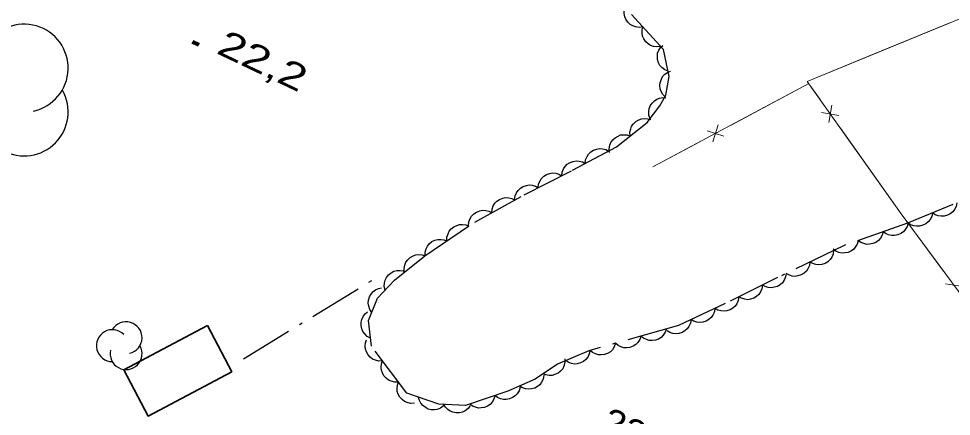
# Model space of a CAD drawing. Extents: x 356765 to 358572, y 5103174 to 5104650.
# Drawn here: x 357286.2 to 357339.2, y 5103854.6 to 5103877.1 of the extents above; entities that cross this region are included whole.
import ezdxf

# ---------------------------------------------------------------- set-up
doc = ezdxf.new("R2010")
doc.units = 0
doc.header["$LTSCALE"] = 0.6
doc.linetypes.add('DOT_DASHED', pattern=[7.7, 5, -1.2, 0.3, -1.2])
for name, color, linetype, lineweight in [('3', 7, 'Continuous', 140), ('31', 7, 'Continuous', 70), ('37', 7, 'Continuous', 13), ('41', 7, 'DOT_DASHED', 25), ('44', 7, 'Continuous', 25)]:
    doc.layers.add(name, color=color, linetype=linetype, lineweight=lineweight)

msp = doc.modelspace()

# ---------------------------------------------------------------- linework, layer by layer
at = {"layer": '3'}
msp.add_line((357296.1, 5103875.8), (357296.46, 5103875.63), dxfattribs=at)
at = {"layer": '31', "lineweight": 35}
msp.add_lwpolyline([(357296.95, 5103859.7), (357298.34, 5103857.08), (357293.6, 5103854.57), (357292.21, 5103857.19), (357296.95, 5103859.7)], close=True, dxfattribs=at)
at = {"layer": '37'}
for p, q in [((357339.09, 5103876.87), (357334.47, 5103874.97)), ((357331.09, 5103873.42), (357322.23, 5103868.7)), ((357331.09, 5103873.42), (357326.68, 5103871.07)), ((357332.22, 5103871.21), (357332.39, 5103872.2)), ((357331.81, 5103871.79), (357332.8, 5103871.62)), ((357325.94, 5103871.08), (357325.65, 5103870.12)), ((357332.88, 5103870.89), (357335.78, 5103866.81)), ((357325.32, 5103870.74), (357326.27, 5103870.45)), ((357324.91, 5103870.13), (357322.23, 5103868.7)), ((357338.84, 5103862.06), (357339.83, 5103861.91))]:
    msp.add_line(p, q, dxfattribs=at)
for points in [[(357345.56, 5103879.54), (357331, 5103873.54), (357336.33, 5103866.04), (357346.74, 5103851.99), (357353.38, 5103842.19), (357364.67, 5103829.93), (357370.13, 5103835.61)], [(357334.47, 5103874.97), (357331, 5103873.54), (357331.73, 5103872.52)], [(357335.78, 5103866.81), (357336.33, 5103866.04), (357338.74, 5103862.78)]]:
    msp.add_lwpolyline(points, dxfattribs=at)
at = {"layer": '41'}
msp.add_line((357299, 5103857.82), (357306.67, 5103862.49), dxfattribs=at)
at = {"layer": '44'}
for points in [[(357321.67, 5103876.64), (357321.46, 5103876.61), (357321.26, 5103876.64), (357321.1, 5103876.69), (357320.95, 5103876.78), (357320.82, 5103876.91), (357320.71, 5103877.07), (357320.64, 5103877.21), (357320.61, 5103877.39), (357320.61, 5103877.57), (357320.66, 5103877.75)], [(357322.68, 5103875.53), (357322.47, 5103875.5), (357322.27, 5103875.53), (357322.11, 5103875.58), (357321.97, 5103875.68), (357321.83, 5103875.8), (357321.73, 5103875.96), (357321.65, 5103876.11), (357321.63, 5103876.28), (357321.63, 5103876.47), (357321.67, 5103876.64)], [(357323.11, 5103874.13), (357322.91, 5103874.21), (357322.75, 5103874.33), (357322.64, 5103874.45), (357322.56, 5103874.61), (357322.51, 5103874.79), (357322.5, 5103874.98), (357322.51, 5103875.14), (357322.58, 5103875.31), (357322.67, 5103875.47), (357322.8, 5103875.59)], [(357322.95, 5103872.65), (357322.8, 5103872.8), (357322.71, 5103872.98), (357322.65, 5103873.13), (357322.63, 5103873.31), (357322.65, 5103873.49), (357322.72, 5103873.67), (357322.79, 5103873.82), (357322.91, 5103873.95), (357323.06, 5103874.06), (357323.23, 5103874.13)], [(357322.08, 5103871.43), (357322.01, 5103871.63), (357322, 5103871.83), (357322.02, 5103871.99), (357322.09, 5103872.16), (357322.19, 5103872.31), (357322.33, 5103872.44), (357322.46, 5103872.54), (357322.62, 5103872.6), (357322.8, 5103872.63), (357322.98, 5103872.62)], [(357320.95, 5103870.45), (357320.93, 5103870.66), (357320.98, 5103870.86), (357321.03, 5103871.01), (357321.14, 5103871.15), (357321.27, 5103871.28), (357321.44, 5103871.37), (357321.59, 5103871.43), (357321.77, 5103871.45), (357321.95, 5103871.43), (357322.13, 5103871.38)], [(357319.77, 5103869.52), (357319.75, 5103869.73), (357319.8, 5103869.93), (357319.86, 5103870.09), (357319.96, 5103870.23), (357320.1, 5103870.35), (357320.26, 5103870.44), (357320.41, 5103870.51), (357320.59, 5103870.52), (357320.78, 5103870.51), (357320.95, 5103870.45)], [(357318.39, 5103868.9), (357318.42, 5103869.1), (357318.5, 5103869.29), (357318.58, 5103869.43), (357318.71, 5103869.55), (357318.86, 5103869.65), (357319.05, 5103869.71), (357319.2, 5103869.75), (357319.38, 5103869.73), (357319.56, 5103869.68), (357319.72, 5103869.6)], [(357317.07, 5103868.19), (357317.09, 5103868.4), (357317.17, 5103868.59), (357317.26, 5103868.73), (357317.38, 5103868.85), (357317.54, 5103868.95), (357317.72, 5103869.01), (357317.88, 5103869.04), (357318.06, 5103869.03), (357318.24, 5103868.98), (357318.39, 5103868.9)], [(357315.73, 5103867.52), (357315.75, 5103867.73), (357315.84, 5103867.91), (357315.92, 5103868.05), (357316.05, 5103868.17), (357316.21, 5103868.27), (357316.39, 5103868.33), (357316.55, 5103868.36), (357316.73, 5103868.34), (357316.91, 5103868.29), (357317.06, 5103868.2)], [(357314.39, 5103866.84), (357314.42, 5103867.05), (357314.5, 5103867.23), (357314.59, 5103867.37), (357314.72, 5103867.49), (357314.87, 5103867.59), (357315.06, 5103867.65), (357315.22, 5103867.68), (357315.39, 5103867.66), (357315.57, 5103867.61), (357315.73, 5103867.52)], [(357313.09, 5103866.1), (357313.11, 5103866.31), (357313.18, 5103866.49), (357313.26, 5103866.64), (357313.39, 5103866.76), (357313.54, 5103866.86), (357313.73, 5103866.93), (357313.88, 5103866.96), (357314.06, 5103866.95), (357314.24, 5103866.9), (357314.4, 5103866.82)], [(357339.5, 5103866.66), (357339.46, 5103866.46), (357339.36, 5103866.28), (357339.26, 5103866.15), (357339.12, 5103866.04), (357338.96, 5103865.96), (357338.77, 5103865.91), (357338.61, 5103865.9), (357338.43, 5103865.93), (357338.26, 5103865.99), (357338.11, 5103866.09)], [(357311.77, 5103865.37), (357311.79, 5103865.58), (357311.87, 5103865.77), (357311.95, 5103865.91), (357312.08, 5103866.03), (357312.23, 5103866.14), (357312.41, 5103866.2), (357312.57, 5103866.24), (357312.75, 5103866.22), (357312.93, 5103866.18), (357313.09, 5103866.1)], [(357338.11, 5103866.09), (357338.07, 5103865.89), (357337.97, 5103865.71), (357337.87, 5103865.58), (357337.73, 5103865.47), (357337.57, 5103865.39), (357337.38, 5103865.34), (357337.22, 5103865.33), (357337.05, 5103865.36), (357336.87, 5103865.42), (357336.72, 5103865.52)], [(357336.72, 5103865.52), (357336.67, 5103865.32), (357336.56, 5103865.15), (357336.46, 5103865.02), (357336.31, 5103864.92), (357336.15, 5103864.84), (357335.96, 5103864.81), (357335.79, 5103864.8), (357335.62, 5103864.84), (357335.45, 5103864.92), (357335.31, 5103865.02)], [(357310.55, 5103864.5), (357310.55, 5103864.71), (357310.61, 5103864.9), (357310.68, 5103865.05), (357310.79, 5103865.19), (357310.94, 5103865.3), (357311.11, 5103865.38), (357311.27, 5103865.43), (357311.44, 5103865.44), (357311.63, 5103865.41), (357311.79, 5103865.34)], [(357335.31, 5103865.02), (357335.26, 5103864.82), (357335.15, 5103864.65), (357335.04, 5103864.52), (357334.9, 5103864.42), (357334.73, 5103864.35), (357334.54, 5103864.31), (357334.38, 5103864.3), (357334.21, 5103864.35), (357334.04, 5103864.42), (357333.89, 5103864.53)], [(357309.31, 5103863.66), (357309.31, 5103863.87), (357309.37, 5103864.06), (357309.44, 5103864.21), (357309.55, 5103864.34), (357309.7, 5103864.46), (357309.87, 5103864.54), (357310.03, 5103864.59), (357310.2, 5103864.59), (357310.38, 5103864.57), (357310.55, 5103864.5)], [(357333.89, 5103864.53), (357333.84, 5103864.32), (357333.73, 5103864.15), (357333.63, 5103864.02), (357333.48, 5103863.92), (357333.32, 5103863.85), (357333.13, 5103863.82), (357332.96, 5103863.81), (357332.79, 5103863.85), (357332.62, 5103863.92), (357332.48, 5103864.03)], [(357332.5, 5103863.97), (357332.47, 5103863.76), (357332.39, 5103863.58), (357332.3, 5103863.44), (357332.17, 5103863.32), (357332.01, 5103863.23), (357331.82, 5103863.17), (357331.66, 5103863.15), (357331.49, 5103863.17), (357331.31, 5103863.22), (357331.15, 5103863.31)], [(357308.13, 5103862.73), (357308.12, 5103862.94), (357308.16, 5103863.13), (357308.22, 5103863.29), (357308.33, 5103863.43), (357308.46, 5103863.56), (357308.63, 5103863.65), (357308.78, 5103863.71), (357308.95, 5103863.73), (357309.14, 5103863.71), (357309.31, 5103863.66)], [(357307.04, 5103861.71), (357306.99, 5103861.92), (357307, 5103862.12), (357307.04, 5103862.28), (357307.12, 5103862.43), (357307.24, 5103862.58), (357307.39, 5103862.7), (357307.53, 5103862.78), (357307.7, 5103862.82), (357307.89, 5103862.83), (357308.06, 5103862.8)], [(357331.15, 5103863.31), (357331.12, 5103863.11), (357331.04, 5103862.92), (357330.95, 5103862.78), (357330.82, 5103862.67), (357330.66, 5103862.57), (357330.47, 5103862.52), (357330.31, 5103862.49), (357330.14, 5103862.51), (357329.96, 5103862.57), (357329.8, 5103862.66)], [(357329.8, 5103862.66), (357329.77, 5103862.46), (357329.69, 5103862.27), (357329.6, 5103862.13), (357329.47, 5103862.02), (357329.31, 5103861.92), (357329.13, 5103861.87), (357328.97, 5103861.84), (357328.79, 5103861.86), (357328.61, 5103861.91), (357328.46, 5103862)], [(357306.28, 5103860.44), (357306.17, 5103860.62), (357306.11, 5103860.81), (357306.08, 5103860.97), (357306.1, 5103861.15), (357306.15, 5103861.33), (357306.25, 5103861.49), (357306.35, 5103861.62), (357306.5, 5103861.72), (357306.67, 5103861.8), (357306.84, 5103861.84)], [(357328.46, 5103862), (357328.43, 5103861.79), (357328.34, 5103861.61), (357328.26, 5103861.47), (357328.12, 5103861.35), (357327.96, 5103861.26), (357327.78, 5103861.2), (357327.62, 5103861.17), (357327.45, 5103861.19), (357327.27, 5103861.25), (357327.11, 5103861.34)], [(357327.11, 5103861.34), (357327.08, 5103861.13), (357327, 5103860.94), (357326.91, 5103860.8), (357326.78, 5103860.69), (357326.62, 5103860.59), (357326.44, 5103860.54), (357326.28, 5103860.51), (357326.1, 5103860.53), (357325.92, 5103860.58), (357325.77, 5103860.67)], [(357306.21, 5103858.99), (357306.03, 5103859.08), (357305.88, 5103859.23), (357305.78, 5103859.36), (357305.72, 5103859.52), (357305.68, 5103859.7), (357305.69, 5103859.89), (357305.72, 5103860.05), (357305.8, 5103860.21), (357305.91, 5103860.36), (357306.05, 5103860.48)], [(357325.76, 5103860.68), (357325.73, 5103860.48), (357325.64, 5103860.29), (357325.55, 5103860.16), (357325.42, 5103860.04), (357325.26, 5103859.95), (357325.07, 5103859.9), (357324.91, 5103859.87), (357324.74, 5103859.9), (357324.56, 5103859.95), (357324.41, 5103860.04)], [(357324.41, 5103860.04), (357324.37, 5103859.84), (357324.28, 5103859.65), (357324.19, 5103859.52), (357324.06, 5103859.4), (357323.9, 5103859.31), (357323.72, 5103859.26), (357323.55, 5103859.23), (357323.38, 5103859.26), (357323.2, 5103859.31), (357323.05, 5103859.4)], [(357321.56, 5103859.11), (357321.5, 5103858.91), (357321.38, 5103858.74), (357321.27, 5103858.62), (357321.12, 5103858.53), (357320.94, 5103858.46), (357320.75, 5103858.44), (357320.59, 5103858.44), (357320.42, 5103858.5), (357320.26, 5103858.58), (357320.12, 5103858.7)], [(357323.01, 5103859.51), (357322.94, 5103859.32), (357322.82, 5103859.15), (357322.71, 5103859.03), (357322.56, 5103858.94), (357322.39, 5103858.87), (357322.2, 5103858.85), (357322.03, 5103858.85), (357321.87, 5103858.91), (357321.7, 5103858.99), (357321.56, 5103859.11)], [(357306.89, 5103857.7), (357306.68, 5103857.69), (357306.49, 5103857.74), (357306.33, 5103857.8), (357306.2, 5103857.91), (357306.07, 5103858.04), (357305.98, 5103858.22), (357305.92, 5103858.37), (357305.91, 5103858.54), (357305.93, 5103858.73), (357305.99, 5103858.9)], [(357320.12, 5103858.7), (357320.05, 5103858.5), (357319.94, 5103858.33), (357319.83, 5103858.21), (357319.67, 5103858.12), (357319.5, 5103858.06), (357319.31, 5103858.04), (357319.15, 5103858.04), (357318.98, 5103858.09), (357318.81, 5103858.17), (357318.68, 5103858.29)], [(357318.67, 5103858.3), (357318.63, 5103858.09), (357318.54, 5103857.91), (357318.44, 5103857.78), (357318.3, 5103857.67), (357318.14, 5103857.59), (357317.95, 5103857.54), (357317.79, 5103857.52), (357317.62, 5103857.56), (357317.44, 5103857.62), (357317.29, 5103857.72)], [(357307.8, 5103856.5), (357307.59, 5103856.49), (357307.39, 5103856.54), (357307.24, 5103856.6), (357307.1, 5103856.71), (357306.97, 5103856.85), (357306.89, 5103857.02), (357306.83, 5103857.17), (357306.82, 5103857.34), (357306.84, 5103857.53), (357306.89, 5103857.7)], [(357317.24, 5103857.81), (357317.24, 5103857.6), (357317.18, 5103857.4), (357317.12, 5103857.25), (357317, 5103857.12), (357316.86, 5103857), (357316.68, 5103856.92), (357316.53, 5103856.87), (357316.35, 5103856.87), (357316.17, 5103856.9), (357316, 5103856.96)], [(357308.7, 5103855.3), (357308.49, 5103855.29), (357308.29, 5103855.34), (357308.14, 5103855.4), (357308, 5103855.51), (357307.88, 5103855.65), (357307.79, 5103855.82), (357307.73, 5103855.97), (357307.72, 5103856.15), (357307.74, 5103856.33), (357307.8, 5103856.5)], [(357316.05, 5103856.88), (357316.01, 5103856.67), (357315.92, 5103856.49), (357315.83, 5103856.35), (357315.69, 5103856.24), (357315.53, 5103856.16), (357315.34, 5103856.11), (357315.18, 5103856.09), (357315, 5103856.12), (357314.83, 5103856.18), (357314.68, 5103856.27)], [(357314.7, 5103856.21), (357314.64, 5103856.01), (357314.54, 5103855.84), (357314.43, 5103855.71), (357314.28, 5103855.62), (357314.11, 5103855.54), (357313.92, 5103855.51), (357313.76, 5103855.5), (357313.59, 5103855.55), (357313.42, 5103855.62), (357313.28, 5103855.73)], [(357310.36, 5103855.15), (357310.19, 5103855.02), (357310, 5103854.95), (357309.84, 5103854.92), (357309.66, 5103854.93), (357309.48, 5103854.97), (357309.32, 5103855.07), (357309.18, 5103855.16), (357309.07, 5103855.3), (357308.99, 5103855.46), (357308.94, 5103855.63)], [(357313.28, 5103855.73), (357313.22, 5103855.53), (357313.11, 5103855.36), (357313.01, 5103855.23), (357312.86, 5103855.14), (357312.69, 5103855.06), (357312.5, 5103855.03), (357312.34, 5103855.02), (357312.17, 5103855.07), (357312, 5103855.14), (357311.86, 5103855.25)], [(357311.87, 5103855.16), (357311.75, 5103854.99), (357311.58, 5103854.87), (357311.44, 5103854.79), (357311.27, 5103854.75), (357311.08, 5103854.75), (357310.89, 5103854.79), (357310.74, 5103854.84), (357310.6, 5103854.94), (357310.47, 5103855.07), (357310.37, 5103855.23)]]:
    msp.add_lwpolyline(points, dxfattribs=at)
at = {"layer": '44', "linetype": 'DOT_DASHED'}
msp.add_lwpolyline([(357343.53, 5103868.32), (357336.69, 5103865.51), (357333.05, 5103864.23), (357329.31, 5103862.42), (357326.35, 5103860.96), (357323.7, 5103859.71), (357318.61, 5103858.27), (357316.82, 5103857.52), (357315.56, 5103856.66), (357314.01, 5103855.98), (357311.61, 5103855.17), (357310.09, 5103855.24), (357308.28, 5103855.86), (357306.26, 5103858.54), (357306.1, 5103859.99), (357306.61, 5103861.26), (357307.57, 5103862.28), (357309.3, 5103863.65), (357312.13, 5103865.57), (357314.94, 5103867.12), (357317.67, 5103868.51), (357320.17, 5103869.84), (357321.91, 5103871.21), (357322.64, 5103872.17), (357322.97, 5103872.76), (357323.17, 5103873.82), (357322.85, 5103875.35), (357321.03, 5103877.34)], dxfattribs=at)
at = {"layer": '44'}
for centre, radius, start, end in [((357286.5596, 5103874.301), 2.489, 282.26917, 149.72626), ((357286.5596, 5103871.812), 2.489, 166.93686, 29.62122), ((357292.3381, 5103859.0132), 0.9053, 282.26917, 149.72626), ((357291.5595, 5103858.5606), 0.9053, 44.11537, 269.80396), ((357292.3381, 5103858.1079), 0.9053, 166.93686, 29.62122)]:
    msp.add_arc(centre, radius, start, end, dxfattribs=at)

# ---------------------------------------------------------------- texts
at = {"layer": '3'}
for s, width, p in [('22,2   ', 1.35, (357297.4, 5103875.17)), ('22,1   ', 1.1, (357319.17, 5103853.76))]:
    msp.add_text(s, height=1.5, rotation=334.619, dxfattribs=dict(at, width=width)).set_placement(p)

doc.saveas('drawing.dxf')
